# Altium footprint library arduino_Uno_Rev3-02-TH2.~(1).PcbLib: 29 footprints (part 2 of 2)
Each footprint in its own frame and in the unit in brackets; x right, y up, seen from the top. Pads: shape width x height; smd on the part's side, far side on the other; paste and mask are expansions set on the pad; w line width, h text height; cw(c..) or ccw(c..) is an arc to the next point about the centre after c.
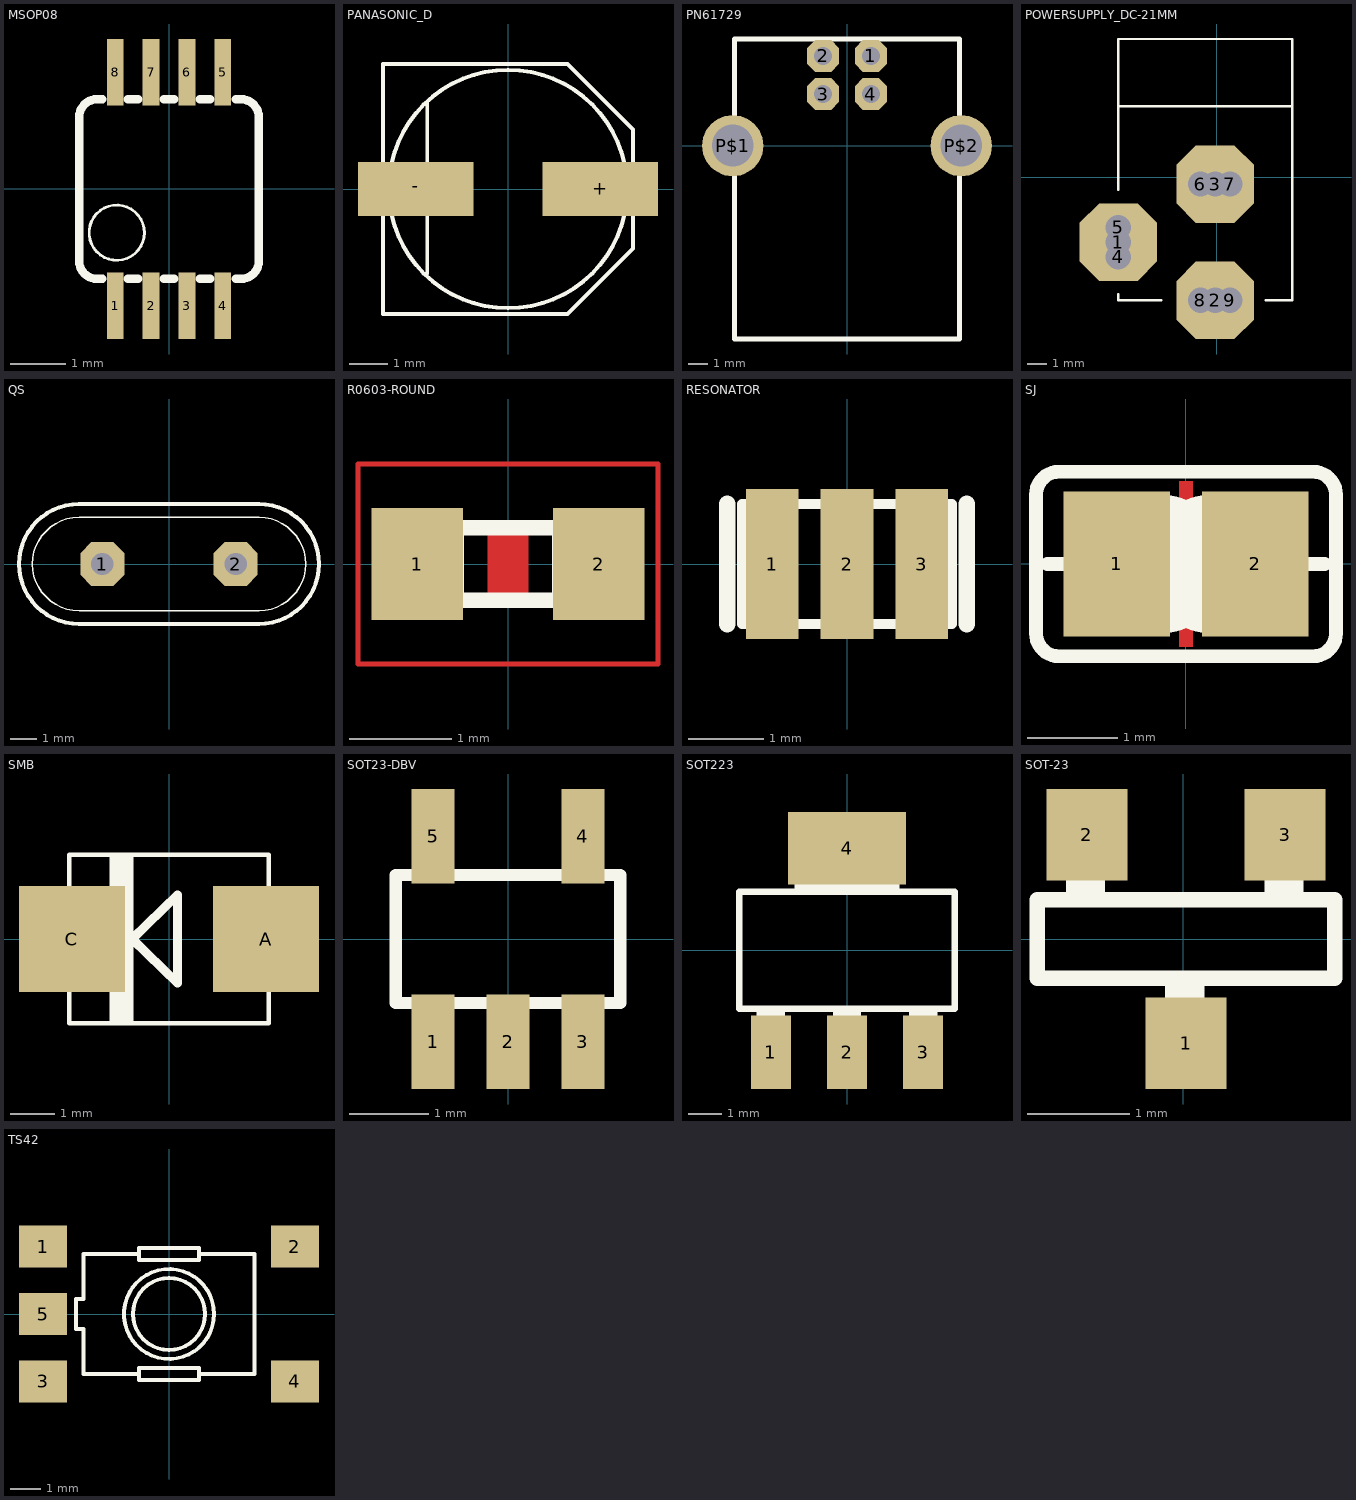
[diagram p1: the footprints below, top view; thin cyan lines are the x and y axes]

## MSOP08 [mm]
pads (8):
  rect 0.3x1.2 smd: 1(-0.976,-2.113) 2(-0.326,-2.113) 3(0.324,-2.113) 4(0.974,-2.113) 5(0.974,2.112) 6(0.324,2.112) 7(-0.326,2.112) 8(-0.976,2.112)
Top Overlay:
  circle w0.051: c-0.946,-0.791 r0.5
  rectangle: -1.098,1.624 -0.854,2.356
  rectangle: -0.447,1.624 -0.204,2.356
  rectangle: 0.203,1.624 0.446,2.356
  rectangle: 0.853,1.624 1.096,2.356
  rectangle: -1.097,-2.357 -0.854,-1.625
  rectangle: -0.447,-2.357 -0.204,-1.626
  rectangle: 0.203,-2.357 0.446,-1.626
  rectangle: 0.853,-2.357 1.096,-1.626
  lines w0.152: -1.341,-1.626 -1.204,-1.626 ; -1.301,-1.626 cw(c-1.301,-1.301) -1.626,-1.301 -1.626,1.299 cw(c-1.301,1.299) -1.301,1.624 -1.204,1.624 ; -0.747,-1.626 -0.554,-1.626 ; -0.747,1.624 -0.554,1.624 ; -0.097,-1.626 0.096,-1.626 ; -0.097,1.624 0.096,1.624 ; 0.553,-1.626 0.746,-1.626 ; 0.553,1.624 0.746,1.624 ; 1.203,-1.626 1.299,-1.626 ccw(c1.299,-1.301) 1.624,-1.301 1.624,1.299 ccw(c1.299,1.299) 1.299,1.624 1.203,1.624

## PANASONIC_D [mm]
pads (2):
  rect 3x1.4 smd: +(2.4,0) -(-2.4,0)
Top Overlay:
  circle w0.102: c0,0 r3.1
  rectangle: 3.05,-0.35 3.65,0.35
  rectangle: -3.65,-0.35 -3.05,0.35
  lines w0.102: -3.25,-0.95 -3.25,-3.25 ; -3.25,0.95 -3.25,3.25 ; -2.95,-0.95 ccw(c0,0) 2.95,-0.95 ; -2.95,0.95 cw(c0,0) 2.95,0.95 ; -2.1,-2.2 -2.1,2.25 ; 3.25,-0.95 3.25,-1.55 ; 3.25,0.95 3.25,1.55 ; -3.25,-3.25 1.55,-3.25 ; -3.25,-3.25 -3.25,3.25 ; -3.25,-3.25 1.55,-3.25 ; -3.25,3.25 1.55,3.25 ; -3.25,3.25 1.55,3.25 ; 1.55,-3.25 3.25,-1.55 ; 1.55,-3.25 3.25,-1.55 ; 1.55,3.25 3.25,1.55 ; 1.55,3.25 3.25,1.55 ; 3.25,-1.55 3.25,1.55

## PN61729 [mil]
pads (6):
  oct 66x66 hole 37.4: 1(49.21,185.43) 2(-49.21,185.43) 3(-49.21,106.69) 4(49.21,106.69)
  round 126.61 hole 86.61: P$1(-236.22,0) P$2(236.22,0)
Top Overlay:
  lines w10: -232.28,-399.61 -232.28,220.47 232.28,220.47 232.28,-399.61 -232.28,-399.61

## POWERSUPPLY_DC-21MM [mm]
pads (9):
  oct 4x4 hole 1.3: 1(-5.08,-3.353) 2(-0.076,-6.35) 3(-0.076,-0.356)
  round 1.95 hole 1.3: 4(-5.08,-4.115) 5(-5.08,-2.591) 6(-0.838,-0.356) 7(0.686,-0.356) 8(-0.838,-6.35) 9(0.686,-6.35)
Top Overlay:
  lines w0.127: -5.08,-6.032 -5.08,-6.35 -2.857,-6.35 ; -5.08,-0.635 -5.08,7.137 3.912,7.137 3.912,3.658 ; -5.055,3.658 3.912,3.658 ; 2.54,-6.35 3.912,-6.35 3.912,3.658

## QS [mil]
pads (2):
  oct 66x66 hole 33.46: 1(-100,0) 2(100,0)
Top Overlay:
  lines w2: -135,-70 cw(c-135,0) -135,70 135,70 cw(c135,0) 135,-70 -135,-70
  lines w6: -135,-90 cw(c-135,0) -135,90 135,90 cw(c135,0) 135,-90 -135,-90

## R0603-ROUND [mil]
pads (2):
  rect 35.37x43.31 smd: 1(-35,0) 2(35,0)
Top Layer:
  rectangle: -7.87,-15.75 7.87,15.75
  lines w2: -57.99,-38.7 57.99,-38.7 57.99,38.7 -57.99,38.7 -57.99,-38.7
Top Overlay:
  rectangle: 17,-17 33,17
  rectangle: -33,-17 -17,17
  lines w6: -17.01,-14.02 17.01,-14.02 ; -17.01,14.02 17.01,14.02

## RESONATOR [mm]
pads (3):
  rect 0.7x2 smd: 1(-1,0) 2(0,0) 3(1,0)
Top Overlay:
  lines w0.127: -1.4,-0.8 1.4,-0.8 1.4,0.8 -1.4,0.8 -1.4,-0.8
  lines w0.22: -1.6,-0.8 -1.6,0.8 ; 1.6,-0.8 1.6,0.8

## SJ [mil]
pads (2):
  rect 46x63 smd: 1(-30,0) 2(30,0)
Top Layer:
  rectangle: -3,-36 3,36
Top Overlay:
  lines w6: -60,0 -40,0 ; 40,0 60,0 ; -65,-30 ccw(c-55,-30) -55,-40 55,-40 ccw(c55,-30) 65,-30 65,30 ccw(c55,30) 55,40 -55,40 ccw(c-55,30) -65,30 -65,-30
  lines w50: -10,-5 cw(c-10,0) -10,5 ; 10,-5 ccw(c10,0) 10,5

## SMB [mm]
pads (2):
  rect 2.4x2.4 smd: A(2.2,0) C(-2.2,0)
Top Overlay:
  rectangle: -2.794,-1.092 -2.261,1.092
  rectangle: 2.261,-1.092 2.794,1.092
  rectangle: -1.35,-1.9 -0.8,1.9
  lines w0.102: -2.261,-1.905 2.261,-1.905 2.261,1.905 -2.261,1.905 -2.261,-1.905
  lines w0.203: -0.83,0 0.193,1 0.193,-1 -0.83,0

## SOT23-DBV [mm]
pads (5):
  rect 0.55x1.2 smd: 1(-0.95,-1.3) 2(0,-1.3) 3(0.95,-1.3) 4(0.95,1.3) 5(-0.95,1.3)
Top Overlay:
  rectangle: -1.2,-1.5 -0.7,-0.85
  rectangle: -0.25,-1.5 0.25,-0.85
  rectangle: 0.7,-1.5 1.2,-0.85
  rectangle: 0.7,0.85 1.2,1.5
  rectangle: -1.2,0.85 -0.7,1.5
  lines w0.152: -1.328,-0.81 -1.422,-0.81 ; -1.328,0.81 -1.422,0.81 ; -0.522,-0.81 -0.428,-0.81 ; -0.522,0.81 0.522,0.81 ; 0.428,-0.81 0.522,-0.81 ; 1.328,-0.81 1.422,-0.81 ; 1.328,0.81 1.422,0.81 ; -1.422,-0.81 1.422,-0.81 ; -1.422,-0.81 -1.422,0.81 ; -1.422,0.81 1.422,0.81 ; 1.422,-0.81 1.422,0.81

## SOT223 [mil]
pads (4):
  rect 48x88 smd: 1(-91,-122) 2(0,-122) 3(91,-122)
  rect 141.73x86.61 smd: 4(0,122.01)
Top Overlay:
  rectangle: -63,71 63,144
  rectangle: -17,-144 17,-71
  rectangle: -108,-144 -74,-71
  rectangle: 74,-144 108,-71
  rectangle: -63,71 63,144
  rectangle: -17,-144 17,-71
  rectangle: -108,-144 -74,-71
  rectangle: 74,-144 108,-71
  lines w8: -129,-70 129,-70 129,70 -129,70 -129,-70

## SOT-23 [mil]
pads (3):
  rect 31x35 smd: 1(1,-40) 2(-37,40) 3(39,40)
Top Overlay:
  rectangle: 31,17 46,37
  rectangle: -45,17 -30,37
  rectangle: -7,-37 8,-17
  lines w6: -56,-15 58,-15 58,15 -56,15 -56,-15

## TS42 [mm]
pads (5):
  rect 1.6x1.4 smd: 1(-4.2,2.25) 2(4.2,2.25) 3(-4.2,-2.25) 4(4.2,-2.25) 5(-4.2,0)
Top Layer:
  rectangle: -4.699,-0.381 -3.81,0.381
Top Overlay:
  circle w0.127: c0,0 r1.5
  circle w0.127: c0,0 r1.2
  lines w0.127: -1,-2 -1,-1.8 1,-1.8 1,-2 ; -1,-2 -1,-2.2 1,-2.2 1,-2 ; -1,-2 -2.85,-2 -2.85,-0.5 -3.1,-0.5 -3.1,0.5 -2.85,0.5 -2.85,2 -1,2 ; -1,2 -1,2.2 1,2.2 1,2 ; -1,2 -1,1.8 1,1.8 1,2 ; 1,-2 2.85,-2 2.85,2 1,2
